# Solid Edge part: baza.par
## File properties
Author: Ionut
Template: Normal.par
Last saved by: Ionut
Revision: 3
Application: Solid Edge
Accuracy: 0.990
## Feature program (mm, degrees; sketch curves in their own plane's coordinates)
sketch for "unnamed Protrusion 1" plane through (0, 0, 0) normal (0, 0, 1) x-axis (1, 0, 0)
  line (-100, -100) -> (100, -100)
  line (100, -100) -> (100, 100)
  line (100, 100) -> (-100, 100)
  line (-100, 100) -> (-100, -100)
  dimension (linear) = 100
  dimension (linear) = 100
extrude "unnamed Protrusion 1" add finite 6 along +normal
sketch for "ExtrudedCutout_1" plane through (0, 0, 6) normal (0, 0, 1) x-axis (1, 0, 0)
  line (-6, -100) -> (6, -100)
  line (6, -100) -> (6, 94)
  line (6, 94) -> (-6, 94)
  line (-6, 94) -> (-6, -100)
  dimension (linear) = 6
extrude "ExtrudedCutout_1" cut finite 3 along -normal
sketch for "ExtrudedProtrusion_2" plane through (0, 0, 6) normal (0, 0, 1) x-axis (1, 0, 0)
  circle centre (20, 60) radius 2
  dimension (linear) = 20
extrude "ExtrudedProtrusion_2" add finite 5 along +normal
sketch for "ExtrudedCutout_2" plane through (0, 94, 4.5) normal (0, -1, 0) x-axis (1, 0, 0)
  circle centre (0, 0) radius 1
extrude "ExtrudedCutout_2" cut finite 56.3864 along -normal
sketch for "ExtrudedProtrusion_3" plane through (0, 0, 6) normal (0, 0, 1) x-axis (0, 1, 0)
extrude "ExtrudedProtrusion_3" add finite 6 along +normal
sketch for "ExtrudedProtrusion_4" plane through (0, 0, 6) normal (0, 0, 1) x-axis (1, 0, 0)
extrude "ExtrudedProtrusion_4" add finite 3 along +normal
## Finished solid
Body 1: solid body, 17 faces, 32 edges, 16 vertices.
  Faces by surface: plane 13, cylinder 4
  Edges by curve: line 24, circle 8
Bounding box of the edges (mm): 200.000 x 200.000 x 12.000, from (-100, -100, 0) to (100, 100, 12).
Cylindrical faces by radius (mm): R1 x1, R2 x2, R6 x1
Planar faces by outward normal: +x 2, +y 1, +z 5, -x 2, -y 2, -z 1
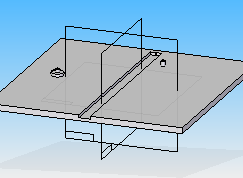
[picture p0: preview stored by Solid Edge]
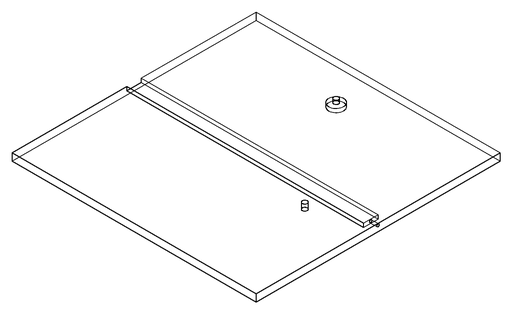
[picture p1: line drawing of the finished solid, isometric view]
